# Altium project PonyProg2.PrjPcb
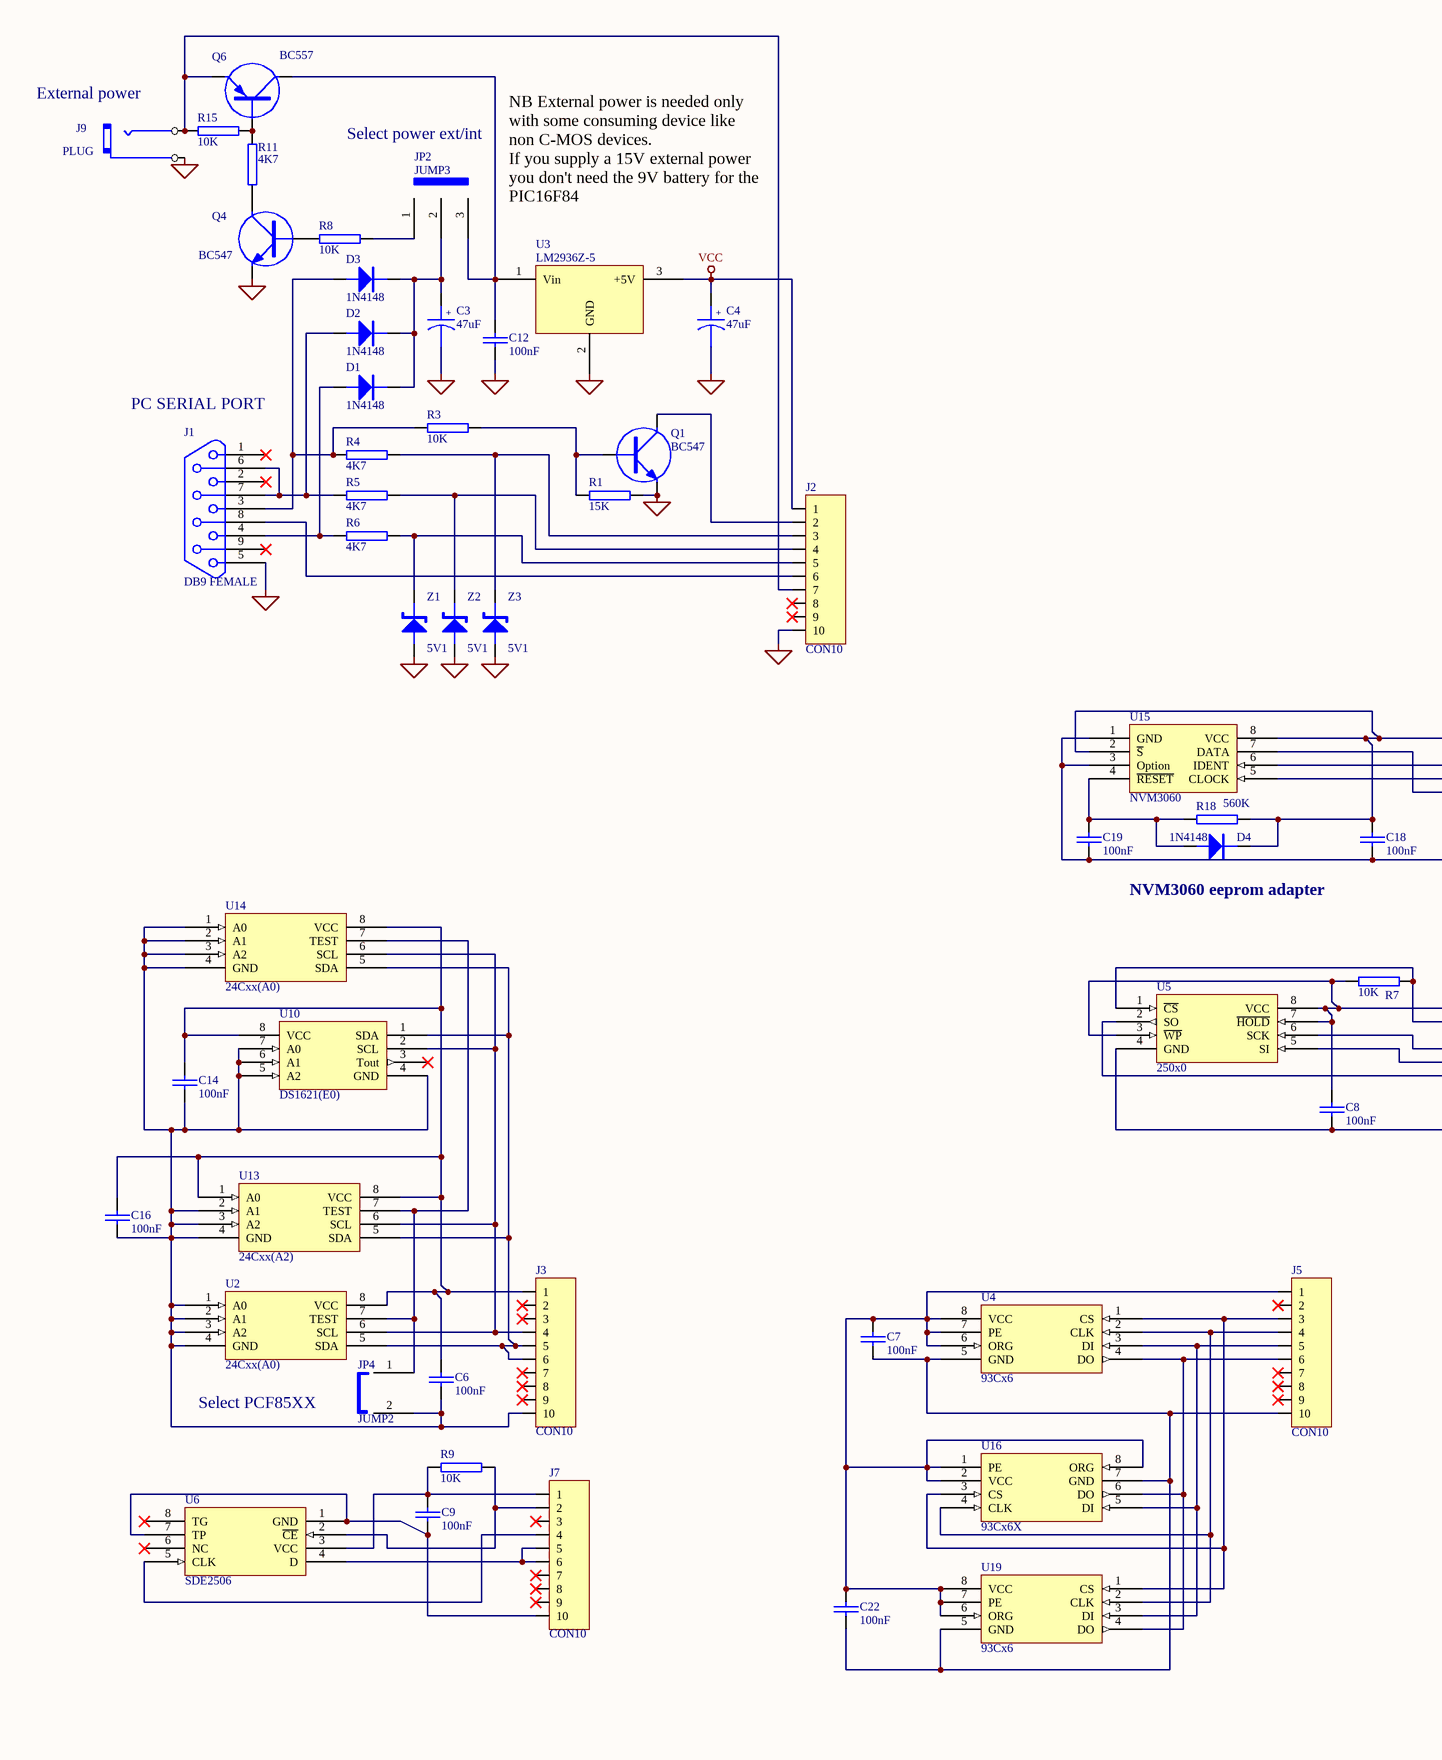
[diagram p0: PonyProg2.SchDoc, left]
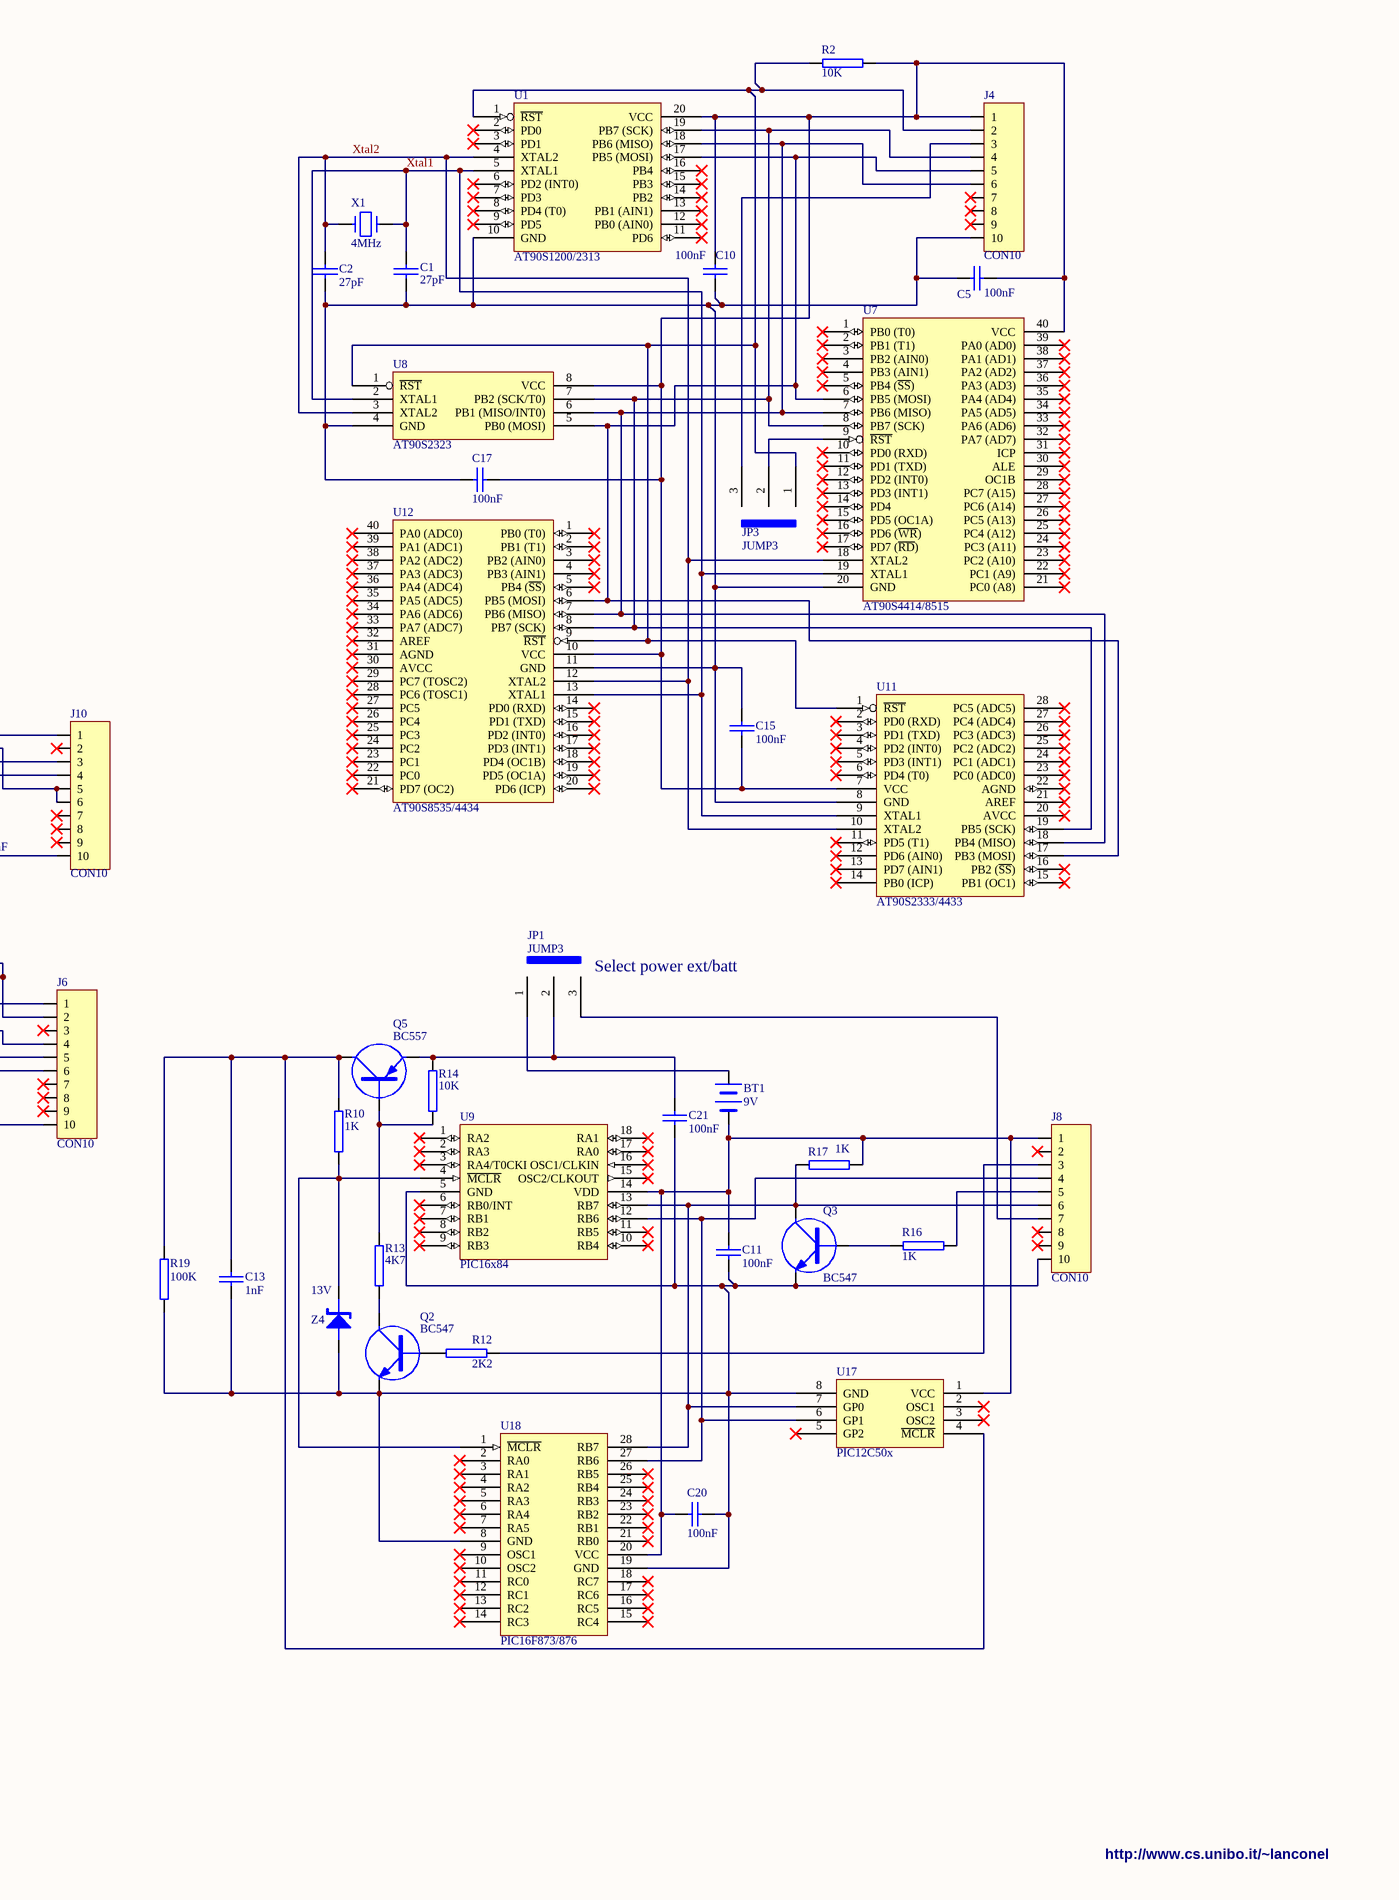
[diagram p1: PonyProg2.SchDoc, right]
1 sheet, 90 parts. Net scope: global (net labels, ports and power ports of the same name join across sheets).
Board file: PonyProg2.PcbDoc

## Sheet PonyProg2.SchDoc: PonyProgrammer - Serial Interface
size A2; Organization: Claudio Lanconelli; Address1: http://www.cs.unibo.it/~lanconel; Address2: lanconel@cs.unibo.it; Address3: Italy; DocumentNumber: 1; Revision: 2.2; SheetNumber: 1; SheetTotal: 1

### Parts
BT1  9V  [SIP2]
C1  27pF  [RAD0.2]
C2  27pF  [RAD0.2]
C3  47uF  [CAPELET1]
C4  47uF  [CAPELET1]
C5  100nF  [RAD0.2]
C6  100nF  [RAD0.2]
C7  100nF  [RAD0.2]
C8  100nF  [RAD0.2]
C9  100nF  [RAD0.2]
C10  100nF  [RAD0.2]
C11  100nF  [RAD0.2]
C12  100nF  [RAD0.2]
C13  1nF  [RAD0.2]
C14  100nF  [RAD0.2]
C15  100nF  [RAD0.2]
C16  100nF  [RAD0.2]
C17  100nF  [RAD0.2]
C18  100nF  [MY-RAD0.2]
C19  100nF  [MY-RAD0.2]
C20  100nF  [MY-RAD0.2]
C21  100nF  [MY-RAD0.2]
C22  100nF  [MY-RAD0.2]
D1  1N4148  [DIODE0.4]
D2  1N4148  [DIODE0.4]
D3  1N4148  [DIODE0.4]
D4  1N4148  [MY-DIODE0.4]
J1  DB9 FEMALE  [DB9RA/F]
J2  CON10  [AMP1X10]
J3  CON10  [SIP10]
J4  CON10  [SIP10]
J5  CON10  [SIP10]
J6  CON10  [SIP10]
J7  CON10  [SIP10]
J8  CON10  [SIP10]
J9  PLUG  [SIP2]
J10  CON10  [MY-SIP10]
JP1  JUMP3  [SIP3]
JP2  JUMP3  [SIP3]
JP3  JUMP3  [SIP3]
JP4  JUMP2  [SIP2]
Q1  BC547  [TO-92A]
Q2  BC547  [TO-92A]
Q3  BC547  [TO-92A]
Q4  BC547  [TO-92A]
Q5  BC557  [TO-92A]
Q6  BC557  [TO-92A]
R1  15K  [AXIAL0.4]
R2  10K  [AXIAL0.4]
R3  10K  [AXIAL0.4]
R4  4K7  [AXIAL0.4]
R5  4K7  [AXIAL0.4]
R6  4K7  [AXIAL0.4]
R7  10K  [AXIAL0.4]
R8  10K  [AXIAL0.4]
R9  10K  [AXIAL0.4]
R10  1K  [AXIAL0.4]
R11  4K7  [AXIAL0.4]
R12  2K2  [AXIAL0.4]
R13  4K7  [AXIAL0.4]
R14  10K  [AXIAL0.4]
R15  10K  [AXIAL0.4]
R16  1K  [AXIAL0.4]
R17  1K  [AXIAL0.4]
R18  560K  [MY-AXIAL0.4]
R19  100K  [MY-AXIAL0.4]
U1  AT90S1200/2313  [DIP20]
U2  24Cxx(A0)  [DIP8]
U3  LM2936Z-5  [TO-92A]
U4  93Cx6  [DIP8]
U5  250x0  [DIP8]
U6  SDE2506  [DIP8]
U7  AT90S4414/8515  [DIP40]
U8  AT90S2323  [MY-DIP8]
U9  PIC16x84  [DIP18]
U10  DS1621(E0)  [DIP8]
U11  AT90S2333/4433  [DIP28S]
U12  AT90S8535/4434  [DIP40]
U13  24Cxx(A2)  [DIP8]
U14  24Cxx(A0)  [SO-8]
U15  NVM3060  [MY-DIP8]
U16  93Cx6X  [MY-SO-8]
U17  PIC12C50x  [MY-DIP8]
U18  PIC16F873/876  [MY-DIP28S]
U19  93Cx6  [MY-SO-8]
X1  4MHz  [XTAL1]
Z1  5V1  [DIODE0.4]
Z2  5V1  [DIODE0.4]
Z3  5V1  [DIODE0.4]
Z4  13V  [DIODE0.4]

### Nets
GND: C3.2 C4.2 C12.2 J1.5 J2.10 J9.2 Q1.1 Q4.1 R1.2 U3.2(GND) Z1.A Z2.A Z3.A
VCC: C4.1 J2.1 U3.3(+5V)
Xtal1: C1.1 U1.5(XTAL1) U7.19(XTAL1) U8.2(XTAL1) U11.9(XTAL1) U12.13(XTAL1) X1.2
Xtal2: C2.1 U1.4(XTAL2) U7.18(XTAL2) U8.3(XTAL2) U11.10(XTAL2) U12.12(XTAL2) X1.1
NetBT1_1: BT1.1 JP1.1
NetBT1_2: BT1.2 C11.1 C20.1 J8.1 R17.1 U9.14(VDD) U17.1(VCC) U18.20(VCC)
NetC1_2: C1.2 C2.2 C5.1 C10.2 C15.2 C17.1 J4.10 U1.10(GND) U7.20(GND) U8.4(GND) U11.8(GND) U12.11(GND)
NetC3_1: C3.1 D1.K D2.K D3.K JP2.2
NetC5_2: C5.2 C10.1 C15.1 C17.2 J4.1 R2.1 U1.20(VCC) U7.40(VCC) U8.8(VCC) U11.7(VCC) U12.10(VCC)
NetC6_1: C6.1 C14.1 C16.1 J3.1 U2.8(VCC) U10.8(VCC) U13.1(A0) U13.8(VCC) U14.8(VCC)
NetC6_2: C6.2 C14.2 C16.2 J3.10 JP4.2 U2.1(A0) U2.2(A1) U2.3(A2) U2.4(GND) U10.4(GND) U10.5(A2) U10.6(A1) U10.7(A0) U13.2(A1) U13.3(A2) U13.4(GND) U14.1(A0) U14.2(A1) U14.3(A2) U14.4(GND)
NetC7_1: C7.1 C22.1 J5.1 U4.6(ORG) U4.7(PE) U4.8(VCC) U16.1(PE) U16.2(VCC) U16.8(ORG) U19.6(ORG) U19.7(PE) U19.8(VCC)
NetC7_2: C7.2 C22.2 J5.10 U4.5(GND) U16.7(GND) U19.5(GND)
NetC8_1: C8.1 J6.1 R7.2 U5.3(~{WP}) U5.7(~{HOLD}) U5.8(VCC)
NetC8_2: C8.2 J6.10 U5.4(GND)
NetC9_1: C9.1 J7.1 R9.2 U6.3(VCC)
NetC9_2: C9.2 J7.10 U6.1(GND) U6.7(TP)
NetC11_2: C11.2 C13.2 C20.2 C21.2 J8.10 Q2.1 Q3.1 R19.1 U9.5(GND) U17.8(GND) U18.8(GND) U18.19(GND) Z4.A
NetC12_1: C12.1 JP2.3 Q6.3 U3.1(Vin)
NetC13_1: C13.1 Q5.3 R10.2 R19.2 U17.4(~{MCLR})
NetC18_1: C18.1 D4.K J10.1 R18.2 U15.2(~{S}) U15.8(VCC)
NetC18_2: C18.2 C19.2 J10.10 U15.1(GND) U15.3(Option)
NetC19_1: C19.1 D4.A R18.1 U15.4(~{RESET})
NetC21_1: C21.1 JP1.2 Q5.1 R14.2
NetD1_A: D1.A J1.4 R6.1
NetD2_A: D2.A J1.6 J1.7 R5.1
NetD3_A: D3.A J1.3 R3.1 R4.1
NetJ1_8: J1.8 J2.6
NetJ2_2: J2.2 Q1.3
NetJ2_3: J2.3 R4.2 Z3.K
NetJ2_4: J2.4 R5.2 Z2.K
NetJ2_5: J2.5 R6.2 Z1.K
NetJ2_7: J2.7 J9.1 Q6.1 R15.2
NetJ3_4: J3.4 U2.6(SCL) U10.2(SCL) U13.6(SCL) U14.6(SCL)
NetJ3_5: J3.5 J3.6 U2.5(SDA) U10.1(SDA) U13.5(SDA) U14.5(SDA)
NetJ4_2: J4.2 JP3.1 R2.2 U1.1(~{RST}) U8.1(~{RST}) U11.1(~{RST}) U12.9(~{RST})
NetJ4_3: J4.3 JP3.3
NetJ4_4: J4.4 U1.19(PB7_(SCK)) U7.8(PB7_(SCK)) U8.7(PB2_(SCK/T0)) U11.19(PB5_(SCK)) U12.8(PB7_(SCK))
NetJ4_5: J4.5 U1.17(PB5_(MOSI)) U7.6(PB5_(MOSI)) U8.5(PB0_(MOSI)) U11.17(PB3_(MOSI)) U12.6(PB5_(MOSI))
NetJ4_6: J4.6 U1.18(PB6_(MISO)) U7.7(PB6_(MISO)) U8.6(PB1_(MISO/INT0)) U11.18(PB4_(MISO)) U12.7(PB6_(MISO))
NetJ5_3: J5.3 U4.1(CS) U16.3(CS) U19.1(CS)
NetJ5_4: J5.4 U4.2(CLK) U16.4(CLK) U19.2(CLK)
NetJ5_5: J5.5 U4.3(DI) U16.5(DI) U19.3(DI)
NetJ5_6: J5.6 U4.4(DO) U16.6(DO) U19.4(DO)
NetJ6_2: J6.2 R7.1 U5.1(~{CS})
NetJ6_4: J6.4 U5.6(SCK)
NetJ6_5: J6.5 U5.5(SI)
NetJ6_6: J6.6 U5.2(SO)
NetJ7_2: J7.2 R9.1 U6.2(~{CE})
NetJ7_4: J7.4 U6.5(CLK)
NetJ7_5: J7.5 J7.6 U6.4(D)
NetJ8_3: J8.3 R12.2
NetJ8_4: J8.4 U9.12(RB6) U17.6(GP1) U18.27(RB6)
NetJ8_5: J8.5 R16.2
NetJ8_6: J8.6 Q3.3 R17.2 U9.13(RB7) U17.7(GP0) U18.28(RB7)
NetJ8_7: J8.7 JP1.3
NetJ10_3: J10.3 U15.6(IDENT)
NetJ10_4: J10.4 U15.5(CLOCK)
NetJ10_5: J10.5 J10.6 U15.7(DATA)
NetJP2_1: JP2.1 R8.1
NetJP3_2: JP3.2 U7.9(~{RST})
NetJP4_1: JP4.1 U2.7(TEST) U13.7(TEST) U14.7(TEST)
NetQ1_2: Q1.2 R1.1 R3.2
NetQ2_2: Q2.2 R12.1
NetQ2_3: Q2.3 R13.1
NetQ3_2: Q3.2 R16.1
NetQ4_2: Q4.2 R8.2
NetQ4_3: Q4.3 R11.1
NetQ5_2: Q5.2 R13.2 R14.1
NetQ6_2: Q6.2 R11.2 R15.1
NetR10_1: R10.1 U9.4(~{MCLR}) U18.1(~{MCLR}) Z4.K

Not connected (* = marked no-connect by the designer): J1 1* 2* 9*; J2 8* 9*; J3 2* 3* 7* 8* 9*; J4 7* 8* 9*; J5 2* 7* 8* 9*; J6 3* 7* 8* 9*; J7 3* 7* 8* 9*; J8 2* 8* 9*; J10 2* 7* 8* 9*; U1 2(PD0)* 3(PD1)* 6(PD2_(INT0))* 7(PD3)* 8(PD4_(T0))* 9(PD5)* 11(PD6)* 12(PB0_(AIN0))* 13(PB1_(AIN1))* 14(PB2)* 15(PB3)* 16(PB4)*; U6 6(NC)* 8(TG)*; U7 1(PB0_(T0))* 2(PB1_(T1))* 3(PB2_(AIN0))* 4(PB3_(AIN1))* 5(PB4_(~{SS}))* 10(PD0_(RXD))* 11(PD1_(TXD))* 12(PD2_(INT0))* 13(PD3_(INT1))* 14(PD4)* 15(PD5_(OC1A))* 16(PD6_(~{WR}))* 17(PD7_(~{RD}))* 21(PC0_(A8))* 22(PC1_(A9))* 23(PC2_(A10))* 24(PC3_(A11))* 25(PC4_(A12))* 26(PC5_(A13))* 27(PC6_(A14))* 28(PC7_(A15))* 29(OC1B)* 30(ALE)* 31(ICP)* 32(PA7_(AD7))* 33(PA6_(AD6))* 34(PA5_(AD5))* 35(PA4_(AD4))* 36(PA3_(AD3))* 37(PA2_(AD2))* 38(PA1_(AD1))* 39(PA0_(AD0))*; U9 1(RA2)* 2(RA3)* 3(RA4/T0CKI)* 6(RB0/INT)* 7(RB1)* 8(RB2)* 9(RB3)* 10(RB4)* 11(RB5)* 15(OSC2/CLKOUT)* 16(OSC1/CLKIN)* 17(RA0)* 18(RA1)*; U10 3(Tout)*; U11 2(PD0_(RXD))* 3(PD1_(TXD))* 4(PD2_(INT0))* 5(PD3_(INT1))* 6(PD4_(T0))* 11(PD5_(T1))* 12(PD6_(AIN0))* 13(PD7_(AIN1))* 14(PB0_(ICP))* 15(PB1_(OC1))* 16(PB2_(~{SS}))* 20(AVCC)* 21(AREF)* 22(AGND)* 23(PC0_(ADC0))* 24(PC1_(ADC1))* 25(PC2_(ADC2))* 26(PC3_(ADC3))* 27(PC4_(ADC4))* 28(PC5_(ADC5))*; U12 1(PB0_(T0))* 2(PB1_(T1))* 3(PB2_(AIN0))* 4(PB3_(AIN1))* 5(PB4_(~{SS}))* 14(PD0_(RXD))* 15(PD1_(TXD))* 16(PD2_(INT0))* 17(PD3_(INT1))* 18(PD4_(OC1B))* 19(PD5_(OC1A))* 20(PD6_(ICP))* 21(PD7_(OC2))* 22(PC0)* 23(PC1)* 24(PC2)* 25(PC3)* 26(PC4)* 27(PC5)* 28(PC6_(TOSC1))* 29(PC7_(TOSC2))* 30(AVCC)* 31(AGND)* 32(AREF)* 33(PA7_(ADC7))* 34(PA6_(ADC6))* 35(PA5_(ADC5))* 36(PA4_(ADC4))* 37(PA3_(ADC3))* 38(PA2_(ADC2))* 39(PA1_(ADC1))* 40(PA0_(ADC0))*; U17 2(OSC1)* 3(OSC2)* 5(GP2)*; U18 2(RA0)* 3(RA1)* 4(RA2)* 5(RA3)* 6(RA4)* 7(RA5)* 9(OSC1)* 10(OSC2)* 11(RC0)* 12(RC1)* 13(RC2)* 14(RC3)* 15(RC4)* 16(RC5)* 17(RC6)* 18(RC7)* 21(RB0)* 22(RB1)* 23(RB2)* 24(RB3)* 25(RB4)* 26(RB5)*

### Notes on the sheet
- External power
- Select power ext/int
- NB External power is needed only with some consuming device like non C-MOS devices.
  If you supply a 15V external power you don't need the 9V battery for the PIC16F84
- (near J1) PC SERIAL PORT
- NVM3060 eeprom adapter
- (near JP1) Select power ext/batt
- Select PCF85XX
- http://www.cs.unibo.it/~lanconel

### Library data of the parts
BT1 = BATTERY
C1 C2 C5-C19 = CAP
C3 C4 = CAPACITOR POL
C20-C22 = CAP-NP
D1-D4 = DIODE
J1 = DB9
Q1-Q4 = NPN
Q5 Q6 = PNP
R1-R12 = RES2
R13-R18 = RES
R19 = STDRES: Standard 1/4W resistor
U1 = AT90S1200: ATMEL AVR AT90S1200
U2 U13 U14 = 24C16
U4 = 93C06
U5 = 25010
U7 = AT90S4414: ATMEL AVR AT90S4414
U8 = AT90S2323: ATMEL AVR micro 2K flash
U9 = PIC16C84
U10 = DS1621
U11 = AT90S2333
U12 = AT90S4434
U16 = MY-93C06X: Microwire serial eeprom
U17 = PIC12C508
U18 = PIC16F873
U19 = MY-93C06: Microwire serial eeprom
X1 = CRYSTAL
Z1-Z4 = ZENER2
